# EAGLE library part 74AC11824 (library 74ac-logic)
9-bit inverting bus interface LATCH
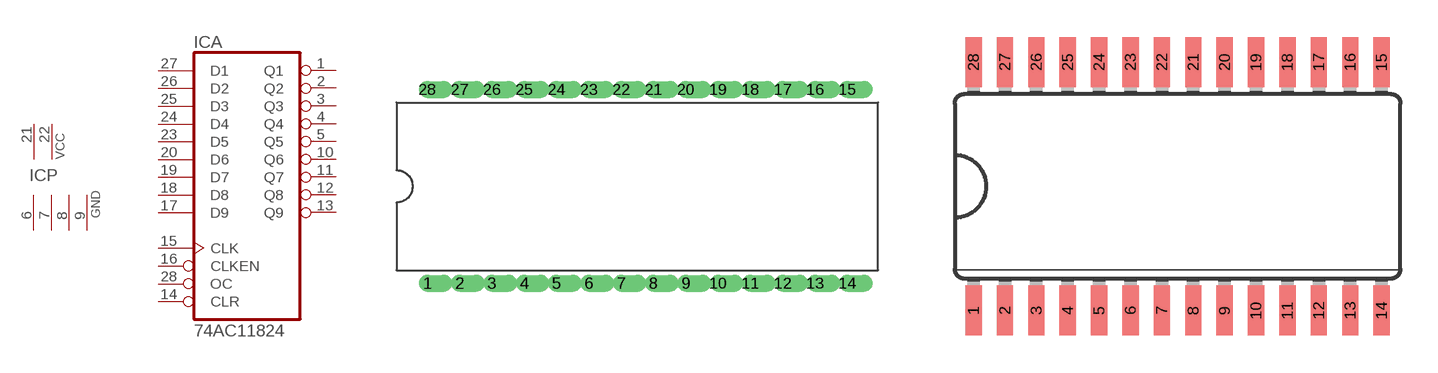
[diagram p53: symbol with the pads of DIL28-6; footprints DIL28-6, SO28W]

Designator prefix IC; gates A=7411824 P=2PWR4GND

## 74AC11824  [DIL28-6]
1  A:Q1  hiz
2  A:Q2  hiz
3  A:Q3  hiz
4  A:Q4  hiz
5  A:Q5  hiz
6  P:GND  pwr
7  P:GND  pwr
8  P:GND  pwr
9  P:GND  pwr
10  A:Q6  hiz
11  A:Q7  hiz
12  A:Q8  hiz
13  A:Q9  hiz
14  A:CLR  in
15  A:CLK  in
16  A:CLKEN  in
17  A:D9  in
18  A:D8  in
19  A:D7  in
20  A:D6  in
21  P:VCC  pwr
22  P:VCC  pwr
23  A:D5  in
24  A:D4  in
25  A:D3  in
26  A:D2  in
27  A:D1  in
28  A:OC  in

## 74AC11824D  [SO28W]
Pads as for DIL28-6

## Footprint DIL28-6 (pad centres in mm)
Dual In Line 0.6 inch
drill 0.813 offset: 1 -16.51,-7.62; 2 -13.97,-7.62; 3 -11.43,-7.62; 4 -8.89,-7.62; 5 -6.35,-7.62; 6 -3.81,-7.62; 7 -1.27,-7.62; 8 1.27,-7.62; 9 3.81,-7.62; 10 6.35,-7.62; 11 8.89,-7.62; 12 11.43,-7.62; 13 13.97,-7.62; 14 16.51,-7.62; 15 16.51,7.62; 16 13.97,7.62; 17 11.43,7.62; 18 8.89,7.62; 19 6.35,7.62; 20 3.81,7.62; 21 1.27,7.62; 22 -1.27,7.62; 23 -3.81,7.62; 24 -6.35,7.62; 25 -8.89,7.62; 26 -11.43,7.62; 27 -13.97,7.62; 28 -16.51,7.62

## Footprint SO28W (pad centres in mm)
Wide Small Outline package 300 mil
smd 0.66 x 2.032: 1 -8.255,-5.029; 2 -6.985,-5.029; 3 -5.715,-5.029; 4 -4.445,-5.029; 5 -3.175,-5.029; 6 -1.905,-5.029; 7 -0.635,-5.029; 8 0.635,-5.029; 9 1.905,-5.029; 10 3.175,-5.029; 11 4.445,-5.029; 12 5.715,-5.029; 13 6.985,-5.029; 14 8.255,-5.029; 15 8.255,5.029; 16 6.985,5.029; 17 5.715,5.029; 18 4.445,5.029; 19 3.175,5.029; 20 1.905,5.029; 21 0.635,5.029; 22 -0.635,5.029; 23 -1.905,5.029; 24 -3.175,5.029; 25 -4.445,5.029; 26 -5.715,5.029; 27 -6.985,5.029; 28 -8.255,5.029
